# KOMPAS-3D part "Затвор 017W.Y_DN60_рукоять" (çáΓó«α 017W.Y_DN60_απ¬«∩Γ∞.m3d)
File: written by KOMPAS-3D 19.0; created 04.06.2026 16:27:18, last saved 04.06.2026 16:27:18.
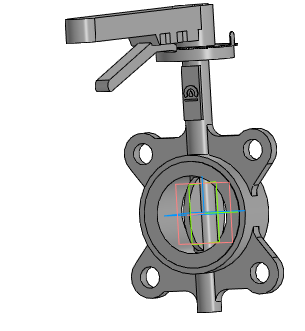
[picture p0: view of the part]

Document properties: Автор: Энергия; Полное имя файла: ..\..\..\3d для проектировщиков\017W разные\x.x Тип 017W.Y(S) Затвор дисковый поворотный межфланцевый\Затвор 017W.Y(S)_DN32-DN350_рукоять\Затвор 017W.Y_DN60_рукоять.a3d

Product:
- Part/product: Затвор 017W.Y_DN60_рукоять
    Масса: 4.11679

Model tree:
1. Операция без истории:1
